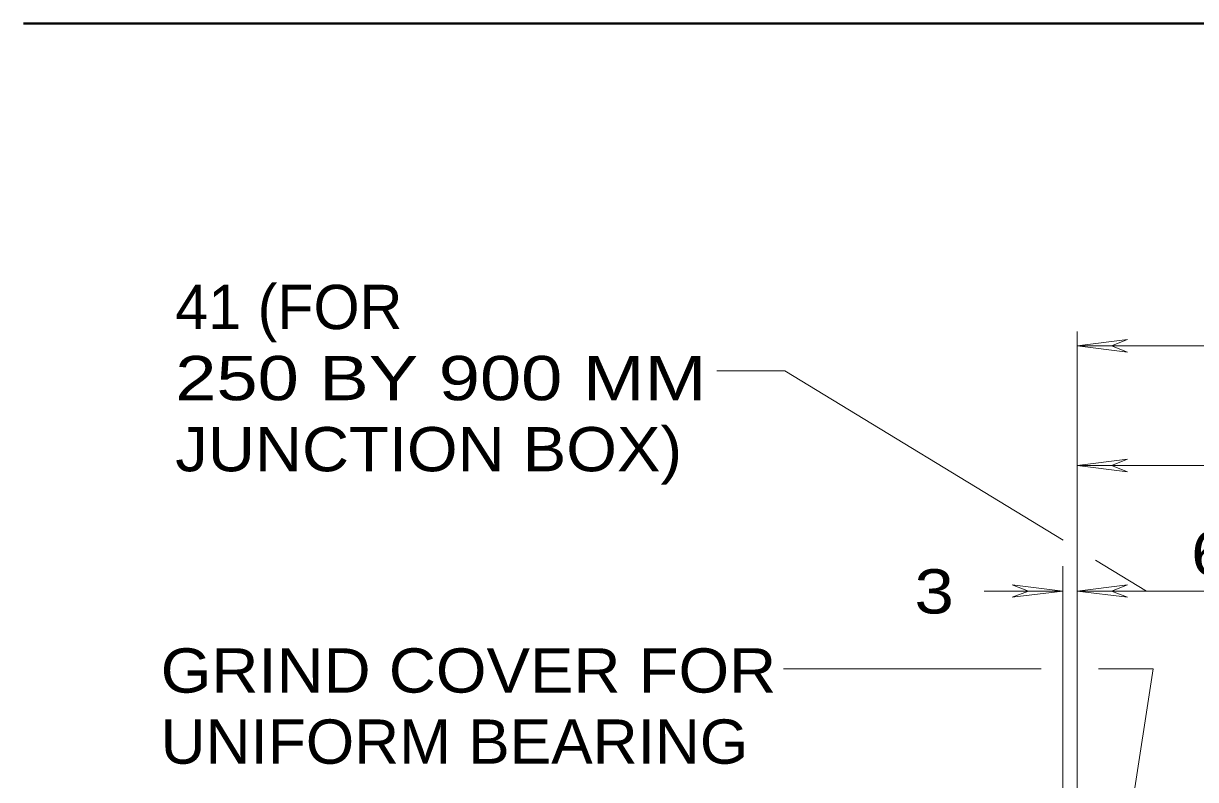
# Model space of a CAD drawing. Extents: x 312583 to 312854, y 144419 to 144597.
# Drawn here: x 312629.36 to 312649.47, y 144476.07 to 144489.05 of the extents above; entities that cross this region are included whole.
import ezdxf

# ---------------------------------------------------------------- set-up
doc = ezdxf.new("R2010")
doc.units = 0
doc.header["$LTSCALE"] = 0.3
doc.layers.add('1', color=7, linetype='Continuous', lineweight=13)

msp = doc.modelspace()

# ---------------------------------------------------------------- linework, layer by layer
at = {"layer": '1', "lineweight": 40}
msp.add_line((312629.3637, 144489.0473), (312702.1235, 144489.0473), dxfattribs=at)
at = {"layer": '1'}
for p, q in [((312647.438, 144475.3431), (312647.438, 144483.7611)), ((312647.438, 144483.5157), (312648.3044, 144483.6231)), ((312648.3044, 144483.6231), (312648.0284, 144483.5157)), ((312647.438, 144483.5157), (312666.2597, 144483.5157)), ((312647.438, 144483.5157), (312648.3044, 144483.4084)), ((312648.3044, 144483.4084), (312648.0284, 144483.5157)), ((312641.2587, 144483.0864), (312642.424, 144483.0864)), ((312642.424, 144483.0864), (312647.2004, 144480.1807)), ((312647.438, 144481.4611), (312648.3044, 144481.5684)), ((312648.3044, 144481.5684), (312648.0284, 144481.4611)), ((312647.438, 144481.4611), (312658.6927, 144481.4611)), ((312647.438, 144481.4611), (312648.3044, 144481.3537)), ((312648.3044, 144481.3537), (312648.0284, 144481.4611)), ((312647.1927, 144475.3431), (312647.1927, 144479.7361)), ((312647.7524, 144479.8357), (312648.6264, 144479.3067)), ((312645.8434, 144479.3067), (312647.1927, 144479.3067)), ((312646.3264, 144479.4141), (312646.6024, 144479.3067)), ((312647.1927, 144479.3067), (312646.3264, 144479.4141)), ((312646.3264, 144479.1994), (312646.6024, 144479.3067)), ((312647.1927, 144479.3067), (312646.3264, 144479.1994)), ((312647.438, 144479.3067), (312648.3044, 144479.4141)), ((312647.438, 144479.3067), (312648.3044, 144479.1994)), ((312648.3044, 144479.4141), (312648.0284, 144479.3067)), ((312648.3044, 144479.1994), (312648.0284, 144479.3067)), ((312642.401, 144477.9727), (312646.8247, 144477.9727)), ((312647.806, 144477.9727), (312648.7414, 144477.9727)), ((312648.7414, 144477.9727), (312648.0437, 144473.4264))]:
    msp.add_line(p, q, dxfattribs=at)
msp.add_lwpolyline([(312647.438, 144479.3067), (312652.4674, 144479.3067), (312657.259, 144479.3067)], dxfattribs=at)

# ---------------------------------------------------------------- texts
msp.add_text('41 (FOR', height=0.76, dxfattribs=at).set_placement((312631.968, 144483.8016))
for s, width, p in [('250 BY 900 MM', 1.25, (312631.968, 144482.5816)), ('JUNCTION BOX)', 1.1, (312631.968, 144481.3616)), ('67 ', 1.2, (312649.3929, 144479.574)), (' 3 ', 1.2, (312644.3087, 144478.9215)), ('GRIND COVER FOR', 1.1, (312631.7182, 144477.5635)), ('UNIFORM BEARING', 1.05, (312631.7182, 144476.3435))]:
    msp.add_text(s, height=0.76, dxfattribs=dict(at, width=width)).set_placement(p)

doc.saveas('drawing.dxf')
